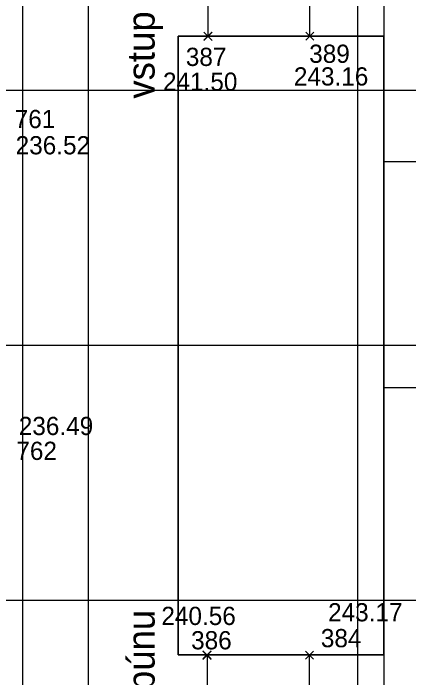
# Model space of a CAD drawing. Extents: x -264205 to -263659, y -1242401 to -1242060.
# Drawn here: x -263811.77 to -263800.91, y -1242163 to -1242144.77 of the extents above; entities that cross this region are included whole.
import ezdxf

# ---------------------------------------------------------------- set-up
doc = ezdxf.new("R2010")
doc.units = 0
for name, color, linetype in [('BOD_CISLO', 7, 'Continuous'), ('BOD_SYMBOL', 7, 'Continuous'), ('BOD_VYSKA', 7, 'Continuous'), ('KFA_SO_10-1_VSTUPY_TRIBUNA_C', 7, 'Continuous'), ('OBRUBNIKY_KOMUNIKACIE_PROJEKT', 7, 'Continuous'), ('OSI_STAVBY_KFA', 7, 'Continuous'), ('POPIS', 7, 'Continuous'), ('SITUACIA_DSP_2D', 7, 'Continuous')]:
    doc.layers.add(name, color=color, linetype=linetype)

msp = doc.modelspace()

# ---------------------------------------------------------------- linework, layer by layer
at = {"layer": 'BOD_SYMBOL'}
for p, q in [((-263806.535, -1242145.508), (-263806.313, -1242145.286)), ((-263806.313, -1242145.508), (-263806.535, -1242145.286)), ((-263806.534, -1242145.511), (-263806.312, -1242145.289)), ((-263806.312, -1242145.511), (-263806.534, -1242145.289)), ((-263803.736, -1242145.502), (-263803.514, -1242145.282)), ((-263803.514, -1242145.502), (-263803.736, -1242145.282)), ((-263806.56, -1242162.482), (-263806.339, -1242162.262)), ((-263806.339, -1242162.482), (-263806.56, -1242162.262)), ((-263806.56, -1242162.494), (-263806.339, -1242162.272)), ((-263806.339, -1242162.494), (-263806.56, -1242162.272)), ((-263803.743, -1242162.491), (-263803.522, -1242162.269)), ((-263803.522, -1242162.491), (-263803.743, -1242162.269))]:
    msp.add_line(p, q, dxfattribs=at)
at = {"layer": 'KFA_SO_10-1_VSTUPY_TRIBUNA_C'}
for p, q in [((-263806.435, -1242141.377), (-263806.423, -1242145.4)), ((-263806.449, -1242162.383), (-263806.437, -1242166.406))]:
    msp.add_line(p, q, dxfattribs=at)
for points in [[(-263806.423, -1242145.4), (-263806.424, -1242145.397), (-263803.625, -1242145.392), (-263803.619, -1242141.374), (-263806.435, -1242141.366), (-263806.435, -1242141.377)], [(-263806.437, -1242166.406), (-263806.438, -1242166.403), (-263803.639, -1242166.398), (-263803.633, -1242162.38), (-263806.449, -1242162.372), (-263806.449, -1242162.383)]]:
    msp.add_lwpolyline(points, dxfattribs=at)
at = {"layer": 'OBRUBNIKY_KOMUNIKACIE_PROJEKT'}
msp.add_line((-263801.593, -1242104.482), (-263801.593, -1242224.282), dxfattribs=at)
at = {"layer": 'OSI_STAVBY_KFA'}
for p, q in [((-263811.518, -1242083.237), (-263811.518, -1242246.707)), ((-263809.718, -1242083.237), (-263809.718, -1242246.707)), ((-263802.318, -1242083.237), (-263802.318, -1242246.707)), ((-263792.653, -1242146.882), (-263909.343, -1242146.882)), ((-263792.653, -1242153.882), (-263909.343, -1242153.882)), ((-263792.653, -1242160.882), (-263909.343, -1242160.882))]:
    msp.add_line(p, q, dxfattribs=at)
at = {"layer": 'SITUACIA_DSP_2D'}
for p, q in [((-263801.593, -1242104.482), (-263801.593, -1242224.282)), ((-263807.243, -1242145.395), (-263807.243, -1242162.369)), ((-263801.593, -1242145.395), (-263807.243, -1242145.395)), ((-263807.243, -1242162.369), (-263807.243, -1242145.395)), ((-263807.243, -1242145.395), (-263801.593, -1242145.395)), ((-263801.593, -1242162.369), (-263801.593, -1242145.395)), ((-263801.593, -1242145.395), (-263801.593, -1242162.369)), ((-263801.593, -1242148.832), (-263800.593, -1242148.832)), ((-263801.593, -1242155.032), (-263800.593, -1242155.032)), ((-263807.243, -1242162.369), (-263801.593, -1242162.369)), ((-263801.593, -1242162.369), (-263807.243, -1242162.369))]:
    msp.add_line(p, q, dxfattribs=at)

# ---------------------------------------------------------------- texts
at = {"layer": 'BOD_CISLO'}
for s, p in [('387', (-263807.031, -1242146.213)), ('389', (-263803.641, -1242146.127)), ('761', (-263811.733, -1242147.918)), ('762', (-263811.688, -1242157.022)), ('386', (-263806.886, -1242162.219)), ('384', (-263803.321, -1242162.161))]:
    msp.add_text(s, height=0.5, dxfattribs=at).set_placement(p)
at = {"layer": 'BOD_VYSKA'}
for s, p in [('243.16', (-263804.062, -1242146.749)), ('241.50', (-263807.659, -1242146.894)), ('236.52', (-263811.707, -1242148.638)), ('236.49', (-263811.621, -1242156.34)), ('240.56', (-263807.703, -1242161.551)), ('243.17', (-263803.122, -1242161.451))]:
    msp.add_text(s, height=0.5, dxfattribs=at).set_placement(p)
at = {"layer": 'POPIS'}
for p in [(-263807.889, -1242147.11), (-263807.889, -1242168.27)]:
    msp.add_text('vstup na tribúnu', height=0.75, rotation=90, dxfattribs=at).set_placement(p)

doc.saveas('drawing.dxf')
